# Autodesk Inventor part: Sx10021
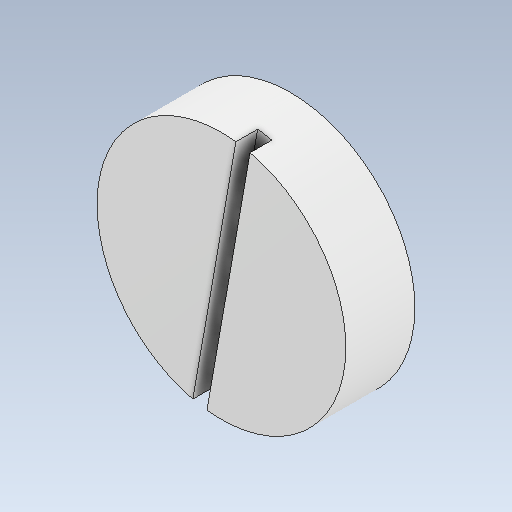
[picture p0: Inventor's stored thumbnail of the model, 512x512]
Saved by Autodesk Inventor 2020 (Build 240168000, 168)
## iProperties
Created: 2021-02
Part Number: Sx10021
Material: Generico
Document SubType Name: Modeling
Designer: zambolin
Density: 1 g/cm^3
Appearance: Default
Author: zambolin
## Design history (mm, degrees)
feature "Solido2"
node "Solido1"
